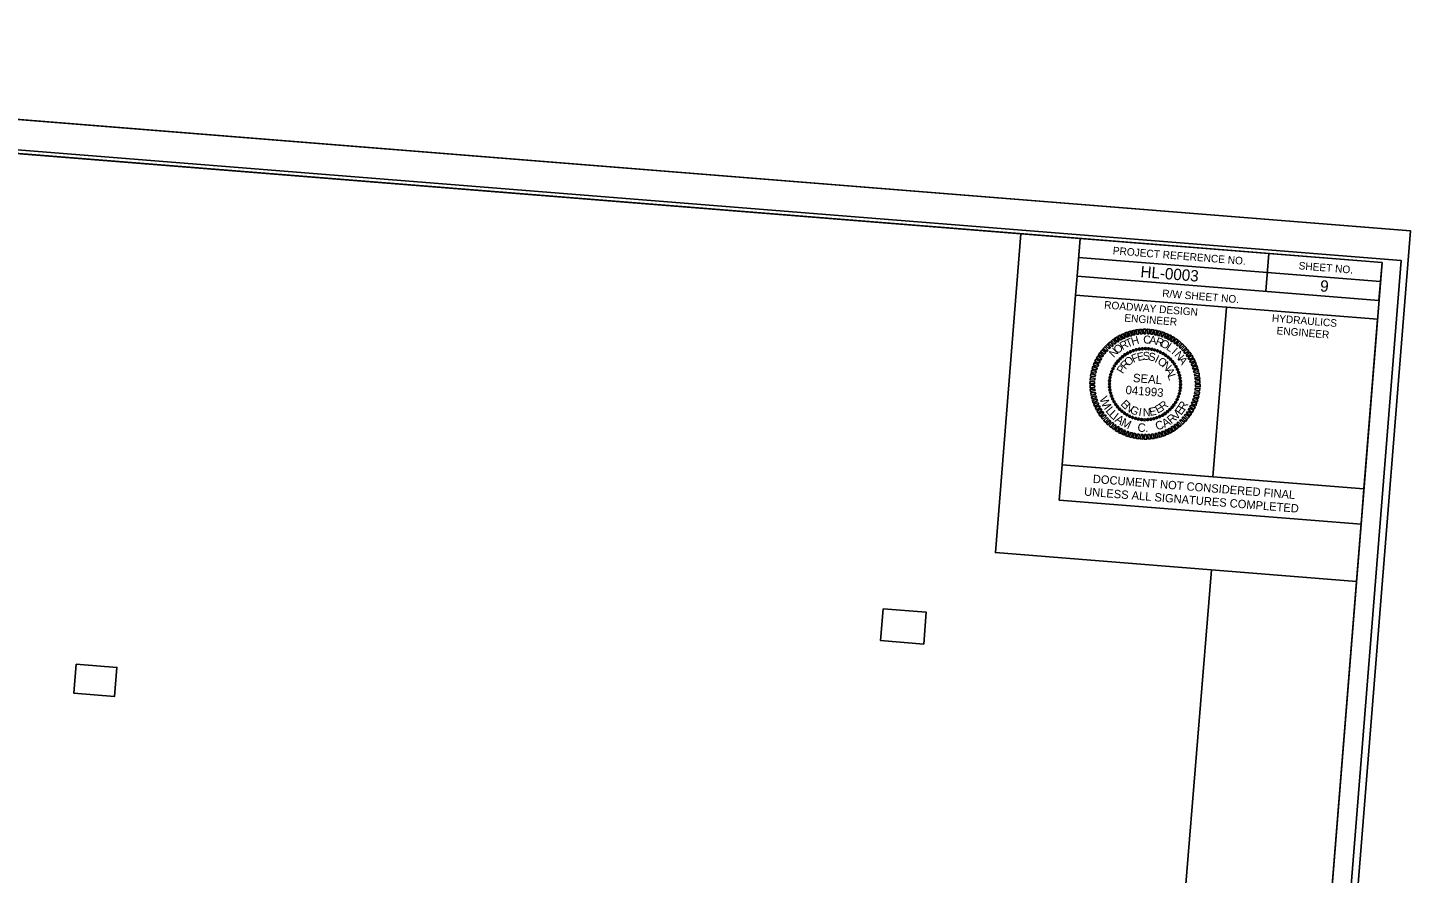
# Model space of a CAD drawing. Extents: x 928111 to 937215, y 683930 to 686530.
# Drawn here: x 935149 to 936063, y 684597 to 685156 of the extents above; entities that cross this region are included whole.
import ezdxf

# ---------------------------------------------------------------- set-up
doc = ezdxf.new("R2010")
doc.units = 0
for name, color, linetype in [('Default', 7, 'Continuous'), ('Matchline', 7, 'Continuous'), ('Prop DSN Text', 7, 'Continuous'), ('Sheet Cutting Line CELL', 7, 'Continuous'), ('Sheet Data Field CELL', 7, 'Continuous'), ('Sheet Layout Plan Border', 7, 'Continuous'), ('Sheet Plan CELL', 7, 'Continuous'), ('Sheet Plan Layout CELL', 7, 'Continuous'), ('Sheet Plot Border Inside CELL', 7, 'Continuous'), ('Sheet Plot Border Outside CELL', 7, 'Continuous')]:
    doc.layers.add(name, color=color, linetype=linetype)

msp = doc.modelspace()

# ---------------------------------------------------------------- linework, layer by layer
at = {"layer": 'Default'}
for p, q in [((935879.64, 684942.06), (935879.64, 684942.06)), ((935881.57, 684942.66), (935881.57, 684942.66)), ((935883.58, 684943.06), (935883.58, 684943.06)), ((935885.66, 684943.27), (935885.66, 684943.27)), ((935887.69, 684943.39), (935887.69, 684943.39)), ((935889.75, 684943.27), (935889.75, 684943.27)), ((935891.8, 684942.97), (935891.8, 684942.97)), ((935893.78, 684942.48), (935893.78, 684942.48)), ((935895.71, 684941.9), (935895.71, 684941.9)), ((935868.29, 684933.56), (935868.29, 684933.56)), ((935869.59, 684935.15), (935869.59, 684935.15)), ((935870.98, 684936.69), (935870.98, 684936.69)), ((935872.5, 684938.02), (935872.5, 684938.02)), ((935874.15, 684939.3), (935874.15, 684939.3)), ((935875.88, 684940.34), (935875.88, 684940.34)), ((935877.74, 684941.27), (935877.74, 684941.27)), ((935897.62, 684941.09), (935897.62, 684941.09)), ((935899.42, 684940.1), (935899.42, 684940.1)), ((935901.17, 684939.02), (935901.17, 684939.02)), ((935902.76, 684937.72), (935902.76, 684937.72)), ((935904.29, 684936.33), (935904.29, 684936.33)), ((935905.63, 684934.81), (935905.63, 684934.81)), ((935906.91, 684933.15), (935906.91, 684933.15)), ((935864.34, 684924.19), (935864.34, 684924.19)), ((935864.83, 684926.17), (935864.83, 684926.17)), ((935865.4, 684928.1), (935865.4, 684928.1)), ((935866.21, 684930.01), (935866.21, 684930.01)), ((935867.21, 684931.82), (935867.21, 684931.82)), ((935907.94, 684931.43), (935907.94, 684931.43)), ((935908.88, 684929.56), (935908.88, 684929.56)), ((935909.67, 684927.67), (935909.67, 684927.67)), ((935910.26, 684925.74), (935910.26, 684925.74)), ((935910.67, 684923.73), (935910.67, 684923.73)), ((935863.92, 684920.09), (935863.92, 684920.09)), ((935864.03, 684922.15), (935864.03, 684922.15)), ((935864.04, 684918.06), (935864.04, 684918.06)), ((935864.25, 684915.97), (935864.25, 684915.97)), ((935887.46, 684919.85), (935887.46, 684919.85)), ((935910.57, 684915.51), (935910.57, 684915.51)), ((935910.88, 684921.64), (935910.88, 684921.64)), ((935910.88, 684917.55), (935910.88, 684917.55)), ((935911, 684919.61), (935911, 684919.61)), ((935864.65, 684913.96), (935864.65, 684913.96)), ((935865.25, 684912.03), (935865.25, 684912.03)), ((935866.04, 684910.14), (935866.04, 684910.14)), ((935866.97, 684908.28), (935866.97, 684908.28)), ((935868.01, 684906.55), (935868.01, 684906.55)), ((935906.63, 684906.14), (935906.63, 684906.14)), ((935907.71, 684907.89), (935907.71, 684907.89)), ((935908.7, 684909.69), (935908.7, 684909.69)), ((935909.51, 684911.6), (935909.51, 684911.6)), ((935910.09, 684913.53), (935910.09, 684913.53)), ((935869.28, 684904.89), (935869.28, 684904.89)), ((935870.62, 684903.37), (935870.62, 684903.37)), ((935872.15, 684901.98), (935872.15, 684901.98)), ((935873.74, 684900.68), (935873.74, 684900.68)), ((935875.49, 684899.6), (935875.49, 684899.6)), ((935877.29, 684898.61), (935877.29, 684898.61)), ((935879.2, 684897.8), (935879.2, 684897.8)), ((935881.13, 684897.22), (935881.13, 684897.22)), ((935883.11, 684896.73), (935883.11, 684896.73)), ((935885.16, 684896.43), (935885.16, 684896.43)), ((935887.22, 684896.31), (935887.22, 684896.31)), ((935889.25, 684896.43), (935889.25, 684896.43)), ((935891.34, 684896.64), (935891.34, 684896.64)), ((935893.34, 684897.04), (935893.34, 684897.04)), ((935895.27, 684897.64), (935895.27, 684897.64)), ((935897.17, 684898.43), (935897.17, 684898.43)), ((935899.03, 684899.36), (935899.03, 684899.36)), ((935900.76, 684900.4), (935900.76, 684900.4)), ((935902.41, 684901.68), (935902.41, 684901.68)), ((935903.93, 684903.01), (935903.93, 684903.01)), ((935905.32, 684904.55), (935905.32, 684904.55))]:
    msp.add_line(p, q, dxfattribs=at)
for points in [[(935869.18, 684947.65), (935867.35, 684950.05), (935868.69, 684950.93), (935870.11, 684948.18)], [(935871.06, 684948.91), (935869.53, 684951.43), (935870.81, 684952.22), (935872.14, 684949.38)], [(935873.21, 684949.91), (935871.69, 684952.57), (935873.2, 684953.2), (935874.15, 684950.4)], [(935875.31, 684950.87), (935874.03, 684953.61), (935875.53, 684954.15), (935876.37, 684951.21)], [(935877.45, 684951.69), (935876.45, 684954.49), (935877.9, 684954.94), (935878.64, 684951.87)], [(935879.8, 684952.25), (935878.95, 684955.14), (935880.43, 684955.45), (935880.8, 684952.5)], [(935882.09, 684952.68), (935881.34, 684955.7), (935882.96, 684955.9), (935883.09, 684952.84)], [(935884.37, 684953.01), (935883.86, 684956.06), (935885.42, 684956.08), (935885.5, 684953.06)], [(935886.64, 684953.12), (935886.36, 684956.15), (935887.97, 684956.21), (935887.77, 684953.17)], [(935888.99, 684953.16), (935889, 684956.22), (935890.54, 684956.05), (935890.11, 684953.03)], [(935891.23, 684952.94), (935891.47, 684955.97), (935893.01, 684955.8), (935892.35, 684952.8)], [(935893.56, 684952.61), (935893.99, 684955.63), (935895.51, 684955.23), (935894.66, 684952.33)], [(935895.77, 684952.06), (935896.43, 684955.01), (935897.95, 684954.66), (935896.88, 684951.83)], [(935898.11, 684951.35), (935898.82, 684954.35), (935900.38, 684953.85), (935899.07, 684951.04)], [(935900.31, 684950.56), (935901.24, 684953.41), (935902.65, 684952.82), (935901.26, 684950.16)], [(935902.34, 684949.56), (935903.65, 684952.41), (935904.91, 684951.75), (935903.39, 684949.14)], [(935904.37, 684948.5), (935905.76, 684951.16), (935907.16, 684950.39), (935905.36, 684947.9)], [(935860.65, 684939.77), (935858.14, 684941.38), (935859.18, 684942.61), (935861.46, 684940.55)], [(935862.2, 684941.53), (935859.8, 684943.32), (935860.8, 684944.6), (935862.88, 684942.37)], [(935863.74, 684943.19), (935861.46, 684945.21), (935862.58, 684946.34), (935864.46, 684943.98)], [(935865.52, 684944.84), (935863.29, 684946.94), (935864.54, 684947.92), (935866.33, 684945.52)], [(935867.19, 684946.35), (935865.3, 684948.57), (935866.51, 684949.6), (935868.13, 684946.93)], [(935906.44, 684947.25), (935907.91, 684949.81), (935909.25, 684948.91), (935907.28, 684946.62)], [(935908.16, 684945.85), (935910.01, 684948.42), (935911.15, 684947.35), (935909.14, 684945.2)], [(935909.96, 684944.29), (935911.9, 684946.72), (935913.03, 684945.6), (935910.8, 684943.56)], [(935911.62, 684942.7), (935913.73, 684944.98), (935914.76, 684943.76), (935912.45, 684941.93)], [(935913.17, 684940.93), (935915.36, 684942.97), (935916.39, 684941.75), (935913.81, 684940.13)], [(935856.28, 684931.61), (935853.43, 684932.45), (935853.88, 684933.96), (935856.73, 684932.56)], [(935857.16, 684933.79), (935854.33, 684934.87), (935855.05, 684936.27), (935857.75, 684934.74)], [(935858.26, 684935.78), (935855.45, 684937.08), (935856.26, 684938.47), (935858.81, 684936.77)], [(935859.36, 684937.85), (935856.79, 684939.23), (935857.61, 684940.62), (935860, 684938.69)], [(935914.67, 684939.12), (935916.99, 684941.05), (935917.87, 684939.71), (935915.25, 684938.13)], [(935915.93, 684937.18), (935918.38, 684938.96), (935919.15, 684937.54), (935916.42, 684936.25)], [(935916.99, 684935.17), (935919.61, 684936.75), (935920.38, 684935.27), (935917.57, 684934.18)], [(935918.04, 684933.02), (935920.79, 684934.44), (935921.28, 684932.95), (935918.53, 684932.08)], [(935854.28, 684922.5), (935851.23, 684922.61), (935851.36, 684924.2), (935854.37, 684923.63)], [(935854.51, 684924.84), (935851.49, 684925.17), (935851.7, 684926.71), (935854.7, 684925.95)], [(935854.93, 684927.06), (935851.96, 684927.58), (935852.27, 684929.15), (935855.25, 684928.16)], [(935855.49, 684929.41), (935852.63, 684930.02), (935853.08, 684931.58), (935855.94, 684930.37)], [(935918.81, 684930.93), (935921.68, 684932.11), (935922.17, 684930.57), (935919.2, 684929.87)], [(935919.48, 684928.67), (935922.43, 684929.66), (935922.83, 684928.17), (935919.87, 684927.65)], [(935920.05, 684926.37), (935923.12, 684927.2), (935923.28, 684925.64), (935920.3, 684925.36)], [(935920.43, 684924.08), (935923.44, 684924.73), (935923.6, 684923.12), (935920.63, 684923.07)], [(935854.14, 684920.16), (935851.07, 684920.03), (935851.11, 684921.63), (935854.14, 684921.29)], [(935854.24, 684917.9), (935851.15, 684917.49), (935851.14, 684919.09), (935854.14, 684919.04)], [(935854.48, 684915.62), (935851.47, 684914.97), (935851.32, 684916.58), (935854.28, 684916.63)], [(935854.86, 684913.33), (935851.79, 684912.5), (935851.63, 684914.06), (935854.62, 684914.34)], [(935920.4, 684914.86), (935923.43, 684914.53), (935923.21, 684912.99), (935920.21, 684913.75)], [(935920.63, 684917.2), (935923.68, 684917.09), (935923.55, 684915.51), (935920.54, 684916.08)], [(935920.67, 684921.8), (935923.76, 684922.21), (935923.77, 684920.61), (935920.77, 684920.67)], [(935920.77, 684919.54), (935923.84, 684919.67), (935923.81, 684918.07), (935920.78, 684918.41)], [(935855.43, 684911.03), (935852.49, 684910.05), (935852.09, 684911.53), (935855.04, 684912.05)], [(935856.1, 684908.77), (935853.23, 684907.59), (935852.74, 684909.13), (935855.71, 684909.83)], [(935856.87, 684906.68), (935854.12, 684905.26), (935853.63, 684906.76), (935856.38, 684907.62)], [(935857.92, 684904.53), (935855.3, 684902.95), (935854.53, 684904.43), (935857.34, 684905.52)], [(935917.75, 684905.91), (935920.58, 684904.83), (935919.86, 684903.43), (935917.16, 684904.97)], [(935918.63, 684908.09), (935921.48, 684907.25), (935921.03, 684905.74), (935918.18, 684907.14)], [(935919.42, 684910.29), (935922.29, 684909.68), (935921.83, 684908.12), (935918.97, 684909.34)], [(935919.99, 684912.64), (935922.95, 684912.12), (935922.64, 684910.55), (935919.66, 684911.54)], [(935858.98, 684902.52), (935856.54, 684900.74), (935855.76, 684902.17), (935858.49, 684903.45)], [(935860.24, 684900.58), (935857.92, 684898.65), (935857.04, 684899.99), (935859.66, 684901.57)], [(935861.74, 684898.77), (935859.56, 684896.74), (935858.52, 684897.95), (935861.1, 684899.57)], [(935863.29, 684897), (935861.18, 684894.72), (935860.15, 684895.94), (935862.46, 684897.77)], [(935864.95, 684895.41), (935863.02, 684892.98), (935861.88, 684894.1), (935864.12, 684896.14)], [(935911.17, 684896.51), (935913.45, 684894.49), (935912.33, 684893.36), (935910.45, 684895.72)], [(935912.71, 684898.17), (935915.11, 684896.38), (935914.11, 684895.1), (935912.04, 684897.33)], [(935914.27, 684899.93), (935916.77, 684898.32), (935915.73, 684897.09), (935913.45, 684899.15)], [(935915.55, 684901.85), (935918.12, 684900.47), (935917.3, 684899.08), (935914.92, 684901.01)], [(935916.65, 684903.92), (935919.47, 684902.62), (935918.65, 684901.23), (935916.11, 684902.93)], [(935866.76, 684893.86), (935864.9, 684891.28), (935863.77, 684892.35), (935865.77, 684894.5)], [(935868.48, 684892.45), (935867, 684889.89), (935865.66, 684890.79), (935867.63, 684893.08)], [(935870.54, 684891.2), (935869.15, 684888.54), (935867.76, 684889.31), (935869.55, 684891.8)], [(935872.57, 684890.15), (935871.26, 684887.29), (935870, 684887.95), (935871.52, 684890.56)], [(935874.61, 684889.14), (935873.67, 684886.3), (935872.26, 684886.88), (935873.65, 684889.54)], [(935876.8, 684888.35), (935876.09, 684885.35), (935874.53, 684885.85), (935875.84, 684888.66)], [(935879.14, 684887.65), (935878.48, 684884.69), (935876.96, 684885.05), (935878.03, 684887.87)], [(935881.36, 684887.09), (935880.93, 684884.07), (935879.41, 684884.47), (935880.25, 684887.37)], [(935883.68, 684886.76), (935883.44, 684883.73), (935881.9, 684883.9), (935882.56, 684886.9)], [(935885.92, 684886.54), (935885.91, 684883.48), (935884.37, 684883.65), (935884.8, 684886.68)], [(935890.54, 684886.69), (935891.05, 684883.64), (935889.5, 684883.62), (935889.41, 684886.64)], [(935892.82, 684887.02), (935893.57, 684884), (935891.96, 684883.8), (935891.82, 684886.87)], [(935895.12, 684887.45), (935895.97, 684884.56), (935894.48, 684884.25), (935894.11, 684887.2)], [(935897.47, 684888.01), (935898.46, 684885.21), (935897.02, 684884.76), (935896.27, 684887.83)], [(935899.6, 684888.83), (935900.89, 684886.09), (935899.38, 684885.56), (935898.54, 684888.49)], [(935901.7, 684889.79), (935903.23, 684887.13), (935901.72, 684886.5), (935900.77, 684889.3)], [(935903.85, 684890.79), (935905.39, 684888.27), (935904.1, 684887.48), (935902.78, 684890.32)], [(935905.74, 684892.05), (935907.57, 684889.65), (935906.23, 684888.77), (935904.8, 684891.52)], [(935907.72, 684893.35), (935909.61, 684891.13), (935908.4, 684890.1), (935906.78, 684892.77)], [(935909.39, 684894.87), (935911.62, 684892.76), (935910.37, 684891.78), (935908.59, 684894.18)], [(935888.28, 684886.59), (935888.55, 684883.55), (935886.95, 684883.49), (935887.14, 684886.54)]]:
    msp.add_lwpolyline(points, close=True, dxfattribs=at)
for centre, major_axis in [((935877.73, 684941.26), (-0.279, 0.615)), ((935879.64, 684942.02), (-0.225, 0.637)), ((935881.6, 684942.62), (-0.168, 0.654)), ((935883.61, 684943.05), (-0.111, 0.666)), ((935885.64, 684943.29), (-0.052, 0.673)), ((935887.69, 684943.36), (0.007, 0.675)), ((935889.74, 684943.25), (0.066, 0.672)), ((935891.77, 684942.96), (0.124, 0.664)), ((935893.77, 684942.5), (0.181, 0.65)), ((935895.72, 684941.86), (0.237, 0.632)), ((935897.61, 684941.06), (0.291, 0.609)), ((935867.21, 684931.81), (-0.581, 0.343)), ((935868.33, 684933.53), (-0.549, 0.393)), ((935869.6, 684935.14), (-0.513, 0.439)), ((935871, 684936.64), (-0.472, 0.482)), ((935872.52, 684938.01), (-0.429, 0.521)), ((935874.16, 684939.24), (-0.382, 0.557)), ((935875.9, 684940.33), (-0.332, 0.588)), ((935899.42, 684940.09), (0.343, 0.581)), ((935901.13, 684938.97), (0.393, 0.549)), ((935902.75, 684937.71), (0.439, 0.513)), ((935904.25, 684936.31), (0.482, 0.472)), ((935905.62, 684934.78), (0.521, 0.429)), ((935906.85, 684933.14), (0.557, 0.382)), ((935864.34, 684924.16), (-0.664, 0.124)), ((935864.81, 684926.16), (-0.65, 0.181)), ((935865.44, 684928.11), (-0.632, 0.237)), ((935866.25, 684930), (-0.609, 0.291)), ((935907.94, 684931.4), (0.588, 0.332)), ((935908.86, 684929.57), (0.615, 0.279)), ((935909.63, 684927.67), (0.637, 0.225)), ((935910.23, 684925.71), (0.654, 0.168)), ((935910.65, 684923.7), (0.666, 0.111)), ((935863.95, 684920.09), (-0.675, 0.007)), ((935864.01, 684918.04), (-0.673, -0.052)), ((935864.06, 684922.13), (-0.672, 0.066)), ((935864.26, 684916), (-0.666, -0.111)), ((935864.69, 684913.99), (-0.654, -0.168)), ((935910.11, 684913.54), (0.65, -0.181)), ((935910.57, 684915.54), (0.664, -0.124)), ((935910.86, 684917.57), (0.672, -0.066)), ((935910.9, 684921.67), (0.673, 0.052)), ((935910.97, 684919.62), (0.675, -0.007)), ((935865.28, 684912.03), (-0.637, -0.225)), ((935866.05, 684910.13), (-0.615, -0.279)), ((935866.98, 684908.3), (-0.588, -0.332)), ((935868.06, 684906.56), (-0.557, -0.382)), ((935869.29, 684904.92), (-0.521, -0.429)), ((935905.32, 684904.56), (0.513, -0.439)), ((935906.58, 684906.17), (0.549, -0.393)), ((935907.7, 684907.89), (0.581, -0.343)), ((935908.67, 684909.7), (0.609, -0.291)), ((935909.47, 684911.59), (0.632, -0.237)), ((935870.67, 684903.39), (-0.482, -0.472)), ((935872.16, 684901.99), (-0.439, -0.513)), ((935873.78, 684900.73), (-0.393, -0.549)), ((935875.5, 684899.61), (-0.343, -0.581)), ((935877.31, 684898.64), (-0.291, -0.609)), ((935879.19, 684897.84), (-0.237, -0.632)), ((935881.14, 684897.2), (-0.181, -0.65)), ((935883.14, 684896.74), (-0.124, -0.664)), ((935885.17, 684896.45), (-0.066, -0.672)), ((935887.22, 684896.34), (-0.007, -0.675)), ((935889.27, 684896.41), (0.052, -0.673)), ((935891.31, 684896.66), (0.111, -0.666)), ((935893.31, 684897.08), (0.168, -0.654)), ((935895.28, 684897.68), (0.225, -0.637)), ((935897.18, 684898.44), (0.279, -0.615)), ((935899.01, 684899.37), (0.332, -0.588)), ((935900.75, 684900.46), (0.382, -0.557)), ((935902.39, 684901.69), (0.429, -0.521)), ((935903.92, 684903.06), (0.472, -0.482))]:
    msp.add_ellipse(centre, major_axis=major_axis, ratio=0.999708, dxfattribs=at)
at = {"layer": 'Matchline'}
msp.add_line((935863.04, 683961.34), (935931.43, 684797.06), dxfattribs=at)
at = {"layer": 'Prop DSN Text'}
for points in [[(935714.38, 684771.33), (935742.9, 684769.05), (935741.22, 684748.06), (935712.7, 684750.34)], [(935181.37, 684734.79), (935208.2, 684732.64), (935206.66, 684713.42), (935179.83, 684715.57)]]:
    msp.add_lwpolyline(points, close=True, dxfattribs=at)
at = {"layer": 'Sheet Cutting Line CELL'}
msp.add_line((936062.74, 685021.28), (934384.6, 685155.51), dxfattribs=at)
at = {"layer": 'Sheet Layout Plan Border'}
msp.add_line((935863.04, 683961.34), (935931.43, 684797.06), dxfattribs=at)
at = {"layer": 'Sheet Plan CELL'}
for p, q in [((935969.19, 685006.14), (935967.25, 684981.22)), ((935843.57, 685003.68), (936042.99, 684987.71)), ((935842.59, 684991.18), (935841.59, 684978.73)), ((935842.59, 684991.18), (936041.99, 684975.25)), ((935830.76, 684843.17), (935832.63, 684866.6)), ((935832.63, 684866.6), (936032.03, 684850.65)), ((936032.03, 684850.64), (936030.16, 684827.21)), ((936030.16, 684827.22), (935830.76, 684843.17))]:
    msp.add_line(p, q, dxfattribs=at)
for points in [[(936044.02, 685000.22), (934548.76, 685119.82), (934465.04, 684073.17), (935960.28, 683953.56)], [(935844.59, 685016.18), (936044.02, 685000.22), (936041.99, 684975.25), (935842.59, 684991.18)], [(935841.59, 684978.73), (935941.32, 684970.75), (935932.35, 684858.6), (935832.63, 684866.6)], [(935941.32, 684970.75), (936040.99, 684962.79), (936032.03, 684850.64), (935932.35, 684858.6)]]:
    msp.add_lwpolyline(points, close=True, dxfattribs=at)
at = {"layer": 'Sheet Plan Layout CELL'}
for points in [[(934548.73, 685119.8), (934465.04, 684073.17), (935960.27, 683953.57), (936027.12, 684789.41), (935788.64, 684808.48), (935805.5, 685019.3)], [(935788.64, 684808.48), (936027.15, 684789.41), (936044.04, 685000.22), (935805.5, 685019.3)]]:
    msp.add_lwpolyline(points, close=True, dxfattribs=at)
at = {"layer": 'Sheet Plot Border Inside CELL'}
msp.add_lwpolyline([(934311.84, 684082.9), (935972.53, 683950.08), (936056.66, 685001.7), (934395.96, 685134.54)], close=True, dxfattribs=at)
at = {"layer": 'Sheet Plot Border Outside CELL'}
msp.add_lwpolyline([(934297.29, 684064), (935975.43, 683929.77), (936062.74, 685021.28), (934384.6, 685155.51)], close=True, dxfattribs=at)

# ---------------------------------------------------------------- texts
at = {"layer": 'Default'}
for s, height, rotation, p in [('H', 5.29, 16.04623, (935879.1, 684945.3)), ('C', 5.29, 1.64662, (935886.35, 684946.6)), ('A', 5.29, 354.44707, (935890.07, 684946.59)), ('R', 5.29, 340.04785, (935893.98, 684946.09)), ('N', 5.29, 44.85025, (935866.78, 684937.02)), ('O', 5.29, 37.64849, (935869.14, 684939.56)), ('R', 5.29, 30.44725, (935872.6, 684942.2)), ('T', 5.29, 23.24652, (935875.94, 684944)), ('O', 5.29, 332.84791, (935897.05, 684945.13)), ('L', 5.29, 325.64762, (935901.02, 684943.08)), ('I', 5.29, 318.44689, (935904.63, 684940.53)), ('N', 5.29, 311.24566, (935906.52, 684938.92)), ('P', 5.29, 58.82564, (935872.84, 684926.38)), ('R', 5.29, 49.4664, (935874.57, 684929.25)), ('O', 5.29, 40.10799, (935876.39, 684931.41)), ('F', 5.29, 21.39378, (935879.69, 684933.92)), ('E', 5.29, 12.03781, (935882.8, 684935.08)), ('S', 5.29, 2.68236, (935886.1, 684935.81)), ('S', 5.29, 353.32715, (935889.47, 684935.58)), ('I', 5.29, 334.61635, (935893.43, 684934.61)), ('O', 5.29, 325.26023, (935895.25, 684933.8)), ('N', 5.29, 315.90336, (935898.23, 684931.69)), ('A', 5.29, 304.0439, (935909.06, 684935.94)), ('SEAL', 5.623, 355.42675, (935879.3, 684921.3)), ('A', 5.29, 297.18701, (935900.7, 684929.04)), ('L', 5.29, 287.8276, (935902.26, 684925.67)), ('041993', 5.623, 355.42675, (935874.42, 684913.36)), ('W', 5.62, 293.78415, (935857.15, 684910.27)), ('I', 5.62, 306.31822, (935859.95, 684903.92)), ('L', 5.62, 310.12017, (935861.07, 684902.13)), ('E', 5.29, 313.70364, (935870.96, 684906.45)), ('N', 5.29, 323.0607, (935873.56, 684903.7)), ('G', 5.29, 332.41699, (935876.95, 684901.32)), ('E', 5.29, 28.55084, (935895.81, 684900.28)), ('R', 5.29, 37.90816, (935899.31, 684902.21)), ('E', 5.62, 55.01382, (935911.36, 684898.9)), ('R', 5.62, 62.12316, (935913.77, 684902.02)), ('L', 5.62, 316.39493, (935863.16, 684899.36)), ('I', 5.62, 322.6697, (935865.55, 684896.82)), ('A', 5.62, 326.47165, (935867.12, 684895.42)), ('M', 5.62, 335.31196, (935871.12, 684892.59)), ('I', 5.29, 351.12795, (935882.92, 684899.05)), ('N', 5.29, 0.48314, (935886.04, 684898.66)), ('E', 5.29, 9.83851, (935890.71, 684898.85)), ('A', 5.62, 30.44024, (935900.48, 684890.86)), ('R', 5.62, 39.28055, (935904.78, 684893.21)), ('V', 5.62, 46.76081, (935908.11, 684895.69)), ('C', 5.62, 357.0418, (935882.37, 684888.48)), ('.', 5.62, 6.62396, (935887.67, 684888.07)), ('C', 5.62, 20.85809, (935895.48, 684889.1))]:
    msp.add_text(s, height=height, rotation=rotation, dxfattribs=at).set_placement(p)
at = {"layer": 'Sheet Data Field CELL'}
for s, p in [('HL-0003', (935884.24, 684990.62)), ('9', (936002.9, 684981.19))]:
    msp.add_text(s, height=7.5, rotation=355.42675, dxfattribs=at).set_placement(p)
at = {"layer": 'Sheet Plan CELL'}
for s, height, p in [('PROJECT REFERENCE NO.', 5.0001, (935866.02, 685005.72)), ('SHEET NO.', 5, (935988.78, 684995.78)), ('R/W SHEET NO.', 5.0001, (935898.67, 684977.47)), ('ROADWAY DESIGN', 5.0001, (935860.32, 684969.91)), ('ENGINEER', 5, (935873.66, 684961.28)), ('HYDRAULICS', 5, (935971.11, 684961.07)), ('ENGINEER', 5, (935974.22, 684952.83)), ('DOCUMENT NOT CONSIDERED FINAL', 5.5, (935852.81, 684854.61)), ('UNLESS ALL SIGNATURES COMPLETED', 5.5, (935847.06, 684846.24))]:
    msp.add_text(s, height=height, rotation=355.42675, dxfattribs=at).set_placement(p)

doc.saveas('drawing.dxf')
